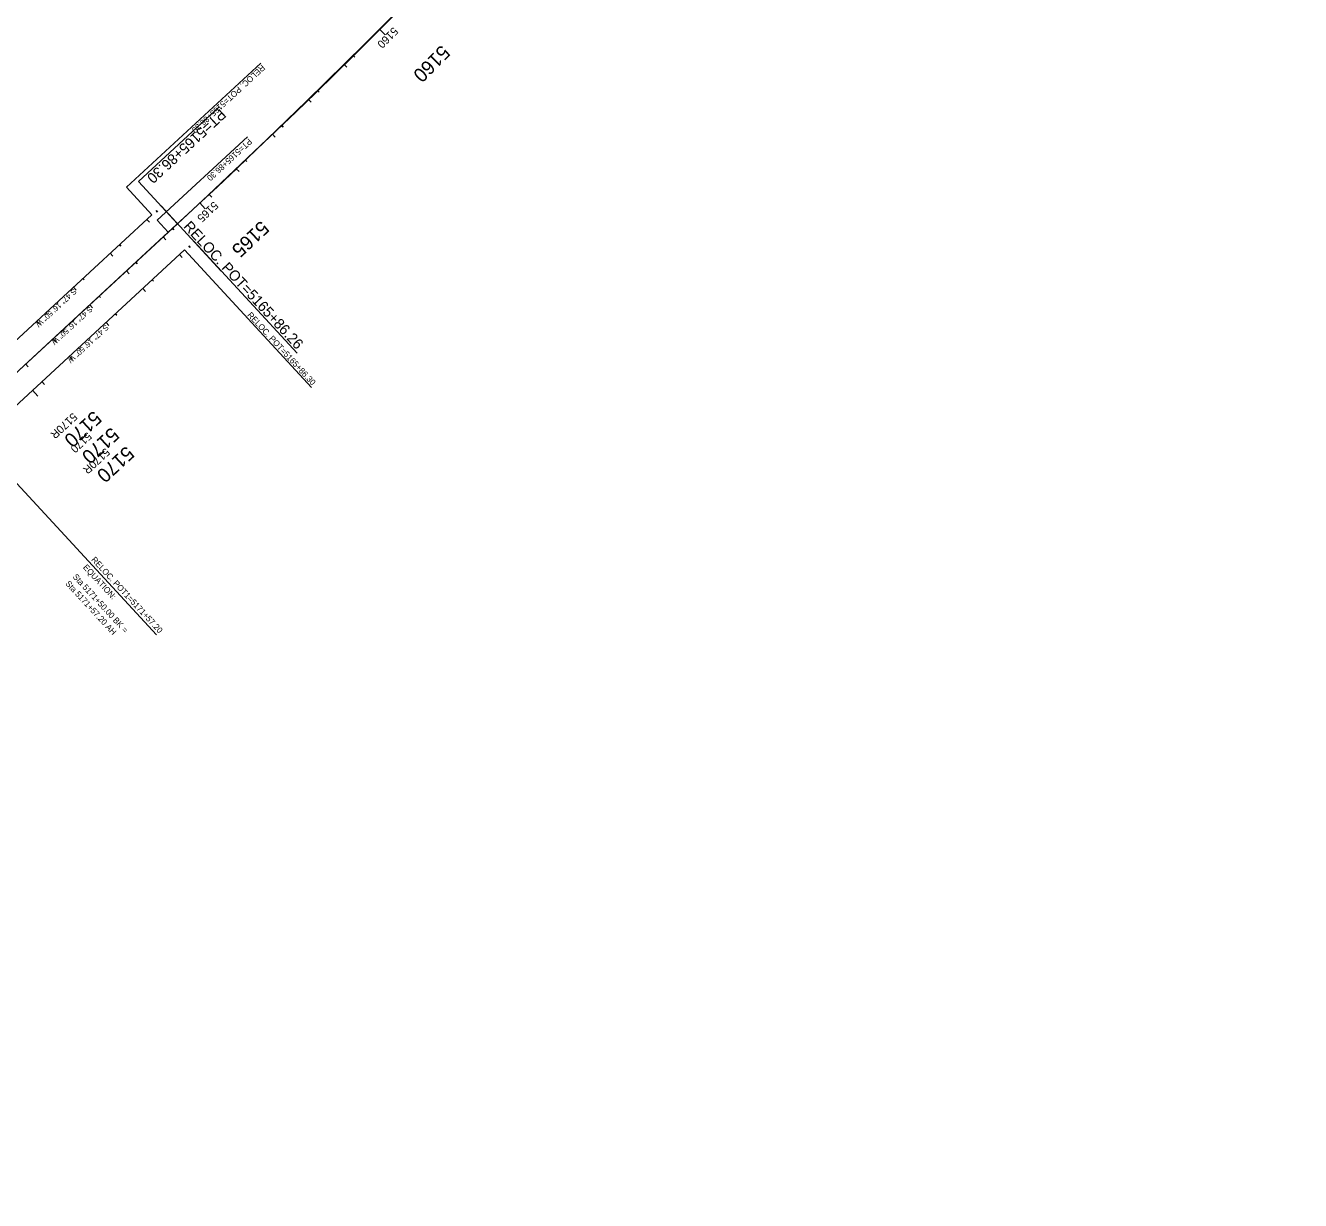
# Model space of a CAD drawing. Extents: x 2160876 to 2175990, y 601436 to 618246.
# Drawn here: x 2172369 to 2174919, y 612185 to 614536 of the extents above; entities that cross this region are included whole.
import ezdxf

# ---------------------------------------------------------------- set-up
doc = ezdxf.new("R2010")
doc.units = 0
for name, color, linetype in [('BNDY-ADJ', 7, 'Continuous'), ('BNDY-ADJ-TXT', 7, 'Continuous'), ('RD_DTM_Major2', 7, 'Continuous'), ('RD_EX_BldgApp_Steps', 7, 'Continuous'), ('RD_EX_DV_TX_Prop', 7, 'Continuous'), ('RD_EX_Parking_Conc', 7, 'Continuous'), ('RD_HC_Cl', 7, 'Continuous'), ('RD_HC_Data_Tic', 7, 'Continuous'), ('RD_HC_TX_Sta50', 7, 'Continuous')]:
    doc.layers.add(name, color=color, linetype=linetype)

msp = doc.modelspace()

# ---------------------------------------------------------------- linework, layer by layer
at = {"layer": 'BNDY-ADJ'}
msp.add_line((2172654, 614122.3), (2172239.9, 613739.9), dxfattribs=at)
msp.add_arc((2162936.5, 624645.9), 14323.9, 312.71947, 326.63611, dxfattribs=at)
at = {"layer": 'BNDY-ADJ-TXT'}
for p, q in [((2172621.5, 614157.6), (2172207.3, 613775.1)), ((2172686.6, 614087), (2172272.5, 613704.6))]:
    msp.add_line(p, q, dxfattribs=at)
at = {"layer": 'RD_DTM_Major2'}
for p, q in [((2173076.5, 614528.8), (2173087.8, 614517.4)), ((2173005.6, 614458.2), (2173011.3, 614452.5)), ((2172934.3, 614388.2), (2172939.9, 614382.4)), ((2172862.4, 614318.6), (2172868, 614312.8)), ((2172790.1, 614249.6), (2172795.6, 614243.8)), ((2172717.3, 614181), (2172728.2, 614169.3)), ((2172644, 614113), (2172649.4, 614107.1)), ((2172570.5, 614045.2), (2172575.9, 614039.3)), ((2172497, 613977.3), (2172502.5, 613971.4)), ((2172423.6, 613909.5), (2172429, 613903.6))]:
    msp.add_line(p, q, dxfattribs=at)
at = {"layer": 'RD_EX_BldgApp_Steps'}
for p, q in [((2173024.3, 614475.5), (2173027.2, 614472.6)), ((2172953, 614405.4), (2172955.8, 614402.6)), ((2172594.7, 614224.1), (2172756.2, 614373.2)), ((2172881.1, 614335.9), (2172883.9, 614333)), ((2172808.8, 614266.8), (2172811.5, 614263.9)), ((2172672.7, 614139.6), (2172594.7, 614224.1)), ((2172736, 614198.3), (2172741.4, 614192.5)), ((2172640, 614175), (2172760.2, 614044.8)), ((2172629.9, 614165.7), (2172632.6, 614162.7)), ((2172672.7, 614139.6), (2163700.6, 605854.7)), ((2172662.7, 614130.3), (2172665.4, 614127.3)), ((2172556.4, 614097.8), (2172559.2, 614094.9)), ((2172695.1, 614095.1), (2172697.8, 614092.1)), ((2172705.2, 614104.4), (2172912, 613880.4)), ((2172589.2, 614062.4), (2172591.9, 614059.5)), ((2172483, 614030), (2172485.7, 614027)), ((2172621.7, 614027.2), (2172624.4, 614024.3)), ((2172515.7, 613994.6), (2172518.4, 613991.7)), ((2172409.5, 613962.1), (2172412.2, 613959.2)), ((2172548.2, 613959.4), (2172550.9, 613956.4)), ((2172442.3, 613926.7), (2172445, 613923.8)), ((2172474.7, 613891.5), (2172477.4, 613888.6)), ((2172368.8, 613858.9), (2172374.2, 613853)), ((2172401.3, 613823.7), (2172406.7, 613817.8))]:
    msp.add_line(p, q, dxfattribs=at)
msp.add_arc((2162955.1, 624663.2), 14324.1, 312.71947, 326.63611, dxfattribs=at)
at = {"layer": 'RD_EX_Parking_Conc'}
for p, q in [((2172631.6, 614146.5), (2172812.4, 614313.5)), ((2172654, 614122.3), (2172631.6, 614146.5))]:
    msp.add_line(p, q, dxfattribs=at)
at = {"layer": 'RD_HC_Cl'}
for p, q in [((2172611.4, 614148.3), (2172616.8, 614142.4)), ((2172537.9, 614080.4), (2172543.4, 614074.5)), ((2172676.5, 614077.7), (2172682, 614071.9)), ((2172464.5, 614012.6), (2172469.9, 614006.7)), ((2172603.1, 614009.9), (2172608.5, 614004)), ((2172391, 613944.7), (2172396.4, 613938.9)), ((2172529.6, 613942.1), (2172535, 613936.2)), ((2172456.1, 613874.2), (2172461.5, 613868.3)), ((2172382.7, 613806.4), (2172393.5, 613794.6))]:
    msp.add_line(p, q, dxfattribs=at)
at = {"layer": 'RD_HC_TX_Sta50'}
for p, q in [((2172570.4, 614212.8), (2172838.9, 614460.8)), ((2172570.4, 614212.8), (2172621.5, 614157.6)), ((2172686.6, 614087), (2172940.7, 613811.9)), ((2172630.4, 613317), (2172272.5, 613704.6))]:
    msp.add_line(p, q, dxfattribs=at)

# ---------------------------------------------------------------- texts
at = {"layer": 'RD_EX_BldgApp_Steps'}
for s, height, rotation, p in [('5160', 28, 225.0647, (2173200.5, 614498.7)), ('PT=5165+86.30', 21, 222.7195, (2172757.6, 614370.5)), ('RELOC. POT=5165+86.26', 21, 312.7195, (2172683.1, 614133)), ('5165', 28, 223.0647, (2172839.5, 614147.2)), ('5170', 28, 222.7195, (2172504.7, 613766.9)), ('5170', 28, 222.7195, (2172539.9, 613733.8)), ('5170', 28, 222.7195, (2172569.9, 613696.3))]:
    msp.add_text(s, height=height, rotation=rotation, dxfattribs=at).set_placement(p)
at = {"layer": 'RD_EX_DV_TX_Prop'}
for s, rotation, p in [('5160', 225.0647, (2173104.3, 614534)), ('5165', 223.0647, (2172745.2, 614185.2)), ('5170', 222.7195, (2172492, 613723.6))]:
    msp.add_text(s, height=16, rotation=rotation, dxfattribs=at).set_placement(p)
at = {"layer": 'RD_EX_Parking_Conc'}
for s, height, p in [('PT=5165+86.30', 12, (2172814.8, 614310.9)), ('S 47° 16\' 50" W', 10.8, (2172496.5, 613974.9))]:
    msp.add_text(s, height=height, rotation=222.7195, dxfattribs=at).set_placement(p)
at = {"layer": 'RD_HC_Data_Tic'}
for p in [(2172463.2, 613762.3), (2172528.3, 613691.8)]:
    msp.add_text('5170R', height=16, rotation=222.7195, dxfattribs=at).set_placement(p)
at = {"layer": 'RD_HC_TX_Sta50'}
for s, height, rotation, p in [('RELOC. POT=5165+86.30', 12, 222.7195, (2172840.9, 614458.6)), ('S 47° 16\' 50" W', 10.8, 222.7195, (2172464.6, 614010.3)), ('RELOC. POT=5165+86.30', 12, 312.7195, (2172811.2, 613956)), ('S 47° 16\' 50" W', 10.8, 222.7195, (2172528.8, 613938.4)), ('EQUATION:', 12, 312.7195, (2172482.7, 613451.3)), ('RELOC. POT1=5171+57.20', 12, 312.7195, (2172499.2, 613466.5)), ('Sta 5171+50.00 BK = ', 12, 312.7195, (2172462.1, 613432.3)), ('Sta 5171+57.20 AH', 12, 312.7195, (2172447.4, 613418.7))]:
    msp.add_text(s, height=height, rotation=rotation, dxfattribs=at).set_placement(p)

doc.saveas('drawing.dxf')
